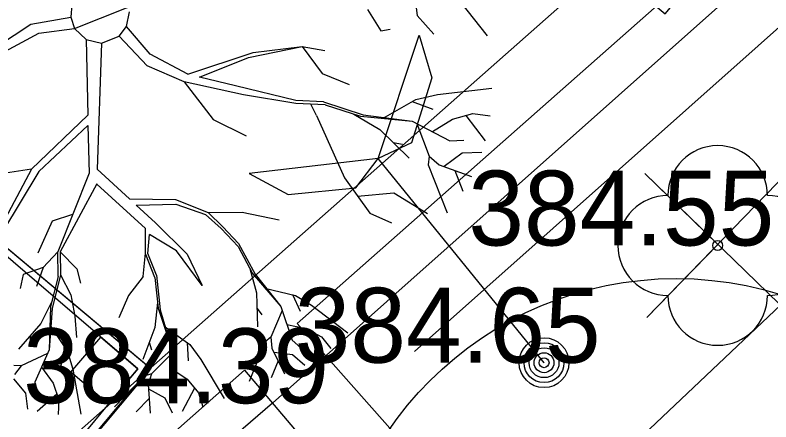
# Model space of a CAD drawing. Extents: x -438233 to -437334, y -1133133 to -1132623.
# Drawn here: x -438067.63 to -438060.06, y -1132995.04 to -1132990.96 of the extents above; entities that cross this region are included whole.
import ezdxf

# ---------------------------------------------------------------- set-up
doc = ezdxf.new("R2010")
doc.units = 0
for name, color, linetype in [('Vrstva 1', 7, 'Continuous'), ('Vrstva 10', 7, 'Continuous'), ('Vrstva 11', 7, 'Continuous'), ('Vrstva 22', 7, 'Continuous'), ('Vrstva 25', 7, 'Continuous'), ('Vrstva 3', 7, 'Continuous'), ('Vrstva 40', 7, 'Continuous'), ('Vrstva 50', 7, 'Continuous'), ('Vrstva 55', 7, 'Continuous'), ('Vrstva 9', 7, 'Continuous')]:
    doc.layers.add(name, color=color, linetype=linetype)

msp = doc.modelspace()

# ---------------------------------------------------------------- linework, layer by layer
at = {"layer": 'Vrstva 1'}
for p, q in [((-438091.5768, -1132973.3017), (-438066.2807, -1132994.4939)), ((-438063.6394, -1132990.6687), (-438063.6015, -1132990.9654)), ((-438063.1685, -1132990.8324), (-438062.8999, -1132991.1694)), ((-438067.0642, -1132990.8541), (-438067.0763, -1132990.9815)), ((-438064.1015, -1132990.9049), (-438063.9684, -1132991.1186)), ((-438067.477, -1132991.0517), (-438067.0763, -1132990.9815)), ((-438067.0763, -1132990.9815), (-438067.0376, -1132991.0961)), ((-438066.5158, -1132991.0767), (-438066.4852, -1132990.9275)), ((-438063.6015, -1132990.9654), (-438063.4346, -1132991.1517)), ((-438067.8141, -1132991.2727), (-438067.477, -1132991.0517)), ((-438067.3972, -1132991.1436), (-438067.0376, -1132991.0961)), ((-438067.0376, -1132991.0961), (-438066.9214, -1132991.2065)), ((-438066.59, -1132991.1719), (-438066.5158, -1132991.0767)), ((-438066.2779, -1132991.3509), (-438066.5158, -1132991.0767)), ((-438063.9684, -1132991.1186), (-438063.8749, -1132991.1009)), ((-438067.7746, -1132991.3468), (-438067.3972, -1132991.1436)), ((-438066.9214, -1132991.2065), (-438066.9045, -1132991.9629)), ((-438066.9214, -1132991.2065), (-438066.7674, -1132991.242)), ((-438066.7674, -1132991.242), (-438066.59, -1132991.1719)), ((-438066.311, -1132991.4678), (-438066.59, -1132991.1719)), ((-438066.7674, -1132991.242), (-438066.8093, -1132992.5048)), ((-438065.2941, -1132991.3864), (-438064.7554, -1132991.2759)), ((-438065.2457, -1132991.3372), (-438064.7554, -1132991.2759)), ((-438064.7554, -1132991.2759), (-438064.5538, -1132991.5476)), ((-438064.7554, -1132991.2759), (-438064.5289, -1132991.317)), ((-438065.9005, -1132991.5541), (-438066.2779, -1132991.3509)), ((-438065.9005, -1132991.5541), (-438065.2457, -1132991.3372)), ((-438065.7844, -1132991.5831), (-438065.2941, -1132991.3864)), ((-438065.9401, -1132991.6283), (-438066.311, -1132991.4678)), ((-438065.4256, -1132991.6702), (-438065.7844, -1132991.5831)), ((-438064.5538, -1132991.5476), (-438064.2845, -1132991.6557)), ((-438065.9401, -1132991.6283), (-438065.6473, -1132992.0065)), ((-438065.3449, -1132991.7597), (-438065.9401, -1132991.6283)), ((-438064.8192, -1132991.8178), (-438065.4256, -1132991.6702)), ((-438063.3999, -1132991.7573), (-438062.8532, -1132991.6928)), ((-438064.8208, -1132991.846), (-438065.3449, -1132991.7597)), ((-438064.5426, -1132991.8299), (-438064.8192, -1132991.8178)), ((-438063.9442, -1132991.9952), (-438063.6176, -1132991.8057)), ((-438063.6176, -1132991.8057), (-438063.3999, -1132991.7573)), ((-438064.524, -1132991.8589), (-438064.8208, -1132991.846)), ((-438064.6111, -1132991.9662), (-438064.6684, -1132991.8525)), ((-438064.5426, -1132991.8299), (-438064.1442, -1132991.9597)), ((-438064.524, -1132991.8589), (-438064.1708, -1132991.9742)), ((-438063.6515, -1132991.825), (-438063.4459, -1132991.9025)), ((-438066.9045, -1132991.9629), (-438067.4706, -1132992.504)), ((-438064.6111, -1132991.9662), (-438064.3329, -1132992.5911)), ((-438064.2377, -1132991.9525), (-438063.9765, -1132992.1065)), ((-438064.1708, -1132991.9742), (-438063.6523, -1132992.0242)), ((-438064.1442, -1132991.9597), (-438063.6523, -1132992.0242)), ((-438063.2499, -1132992.0025), (-438063.0451, -1132991.9468)), ((-438063.1152, -1132991.9662), (-438062.9201, -1132992.2194)), ((-438063.0451, -1132991.9468), (-438062.8693, -1132991.9686)), ((-438065.6473, -1132992.0065), (-438065.3175, -1132992.1702)), ((-438063.6523, -1132992.0242), (-438063.2741, -1132992.2202)), ((-438063.6071, -1132992.0476), (-438063.4829, -1132992.3726)), ((-438063.4499, -1132992.1282), (-438063.2499, -1132992.0025)), ((-438066.9029, -1132992.0678), (-438067.3948, -1132992.529)), ((-438066.9029, -1132992.0678), (-438066.8908, -1132992.5444)), ((-438063.9765, -1132992.1065), (-438063.6845, -1132992.3936)), ((-438063.8426, -1132992.2379), (-438063.7491, -1132992.2532)), ((-438063.2741, -1132992.2202), (-438063.1346, -1132992.2153)), ((-438063.3313, -1132992.4758), (-438063.1523, -1132992.3411)), ((-438063.1523, -1132992.3411), (-438062.9556, -1132992.3331)), ((-438063.4829, -1132992.3726), (-438063.4934, -1132992.4605)), ((-438063.4829, -1132992.3726), (-438063.383, -1132992.4597)), ((-438067.4706, -1132992.504), (-438067.7948, -1132993.1072)), ((-438067.4706, -1132992.504), (-438067.7303, -1132992.5435)), ((-438066.8093, -1132992.5048), (-438066.4868, -1132992.8024)), ((-438063.4934, -1132992.4605), (-438063.3031, -1132992.9411)), ((-438063.383, -1132992.4597), (-438063.0596, -1132992.5782)), ((-438067.3948, -1132992.529), (-438067.7585, -1132993.1306)), ((-438066.8908, -1132992.5444), (-438067.2053, -1132993.333)), ((-438063.2257, -1132992.5177), (-438063.1435, -1132992.7234)), ((-438066.8134, -1132992.6508), (-438067.1819, -1132993.3322)), ((-438066.8142, -1132992.654), (-438066.3255, -1132993.0992)), ((-438064.3329, -1132992.5911), (-438064.0765, -1132992.9459)), ((-438066.4868, -1132992.8024), (-438066.0263, -1132992.8089)), ((-438066.0263, -1132992.8089), (-438065.6997, -1132992.9379)), ((-438064.2015, -1132992.7734), (-438063.8353, -1132992.7403)), ((-438063.8353, -1132992.7403), (-438063.5007, -1132992.9476)), ((-438066.4199, -1132992.8645), (-438066.0207, -1132992.8548)), ((-438066.4199, -1132992.8645), (-438066.2263, -1132993.0427)), ((-438066.0207, -1132992.8548), (-438065.7247, -1132992.958)), ((-438067.0569, -1132992.9596), (-438067.2609, -1132993.0258)), ((-438065.7247, -1132992.958), (-438065.5691, -1132993.0992)), ((-438065.6997, -1132992.9379), (-438065.3578, -1132992.9338)), ((-438065.6997, -1132992.9379), (-438065.5522, -1132993.083)), ((-438065.3578, -1132992.9338), (-438064.9869, -1132993.0129)), ((-438064.0765, -1132992.9459), (-438063.8595, -1132993.0411)), ((-438067.2609, -1132993.0258), (-438067.4061, -1132993.3475)), ((-438066.3247, -1132993.3475), (-438066.3255, -1132993.0992)), ((-438066.2263, -1132993.0427), (-438065.907, -1132993.3564)), ((-438065.3981, -1132993.2782), (-438065.5691, -1132993.0992)), ((-438065.5522, -1132993.083), (-438065.3925, -1132993.25)), ((-438066.3021, -1132993.3508), (-438066.286, -1132993.1588)), ((-438066.0142, -1132993.3209), (-438066.286, -1132993.1588)), ((-438065.3925, -1132993.25), (-438065.228, -1132993.5572)), ((-438067.2053, -1132993.333), (-438067.3529, -1132993.4903)), ((-438067.2005, -1132993.5798), (-438067.2053, -1132993.333)), ((-438067.1819, -1132993.3322), (-438067.0158, -1132993.5015)), ((-438067.1819, -1132993.3322), (-438067.1771, -1132993.5628)), ((-438065.7586, -1132993.6693), (-438066.0142, -1132993.3209)), ((-438065.3981, -1132993.2782), (-438065.2522, -1132993.5507)), ((-438060.59, -1132993.269), (-438060.59, -1132993.269)), ((-438066.3481, -1132993.5782), (-438066.3247, -1132993.3475)), ((-438066.232, -1132993.5886), (-438066.3239, -1132993.3596)), ((-438066.2166, -1132993.5653), (-438066.3021, -1132993.3508)), ((-438065.907, -1132993.3564), (-438065.7586, -1132993.6693)), ((-438067.3529, -1132993.4903), (-438067.552, -1132993.558)), ((-438067.3529, -1132993.4903), (-438067.4198, -1132993.6814)), ((-438067.552, -1132993.558), (-438067.5843, -1132993.6983)), ((-438067.1771, -1132993.5628), (-438067.2634, -1132993.9007)), ((-438067.1771, -1132993.5628), (-438067.0763, -1132993.7628)), ((-438067.0158, -1132993.5015), (-438066.9771, -1132993.6459)), ((-438066.2166, -1132993.5653), (-438066.1796, -1132993.9128)), ((-438065.2796, -1132993.4991), (-438065.2119, -1132993.7435)), ((-438065.2522, -1132993.5507), (-438064.9691, -1132993.8806)), ((-438065.228, -1132993.5572), (-438064.9691, -1132993.8806)), ((-438067.2005, -1132993.5798), (-438067.2771, -1132993.8789)), ((-438066.3481, -1132993.5782), (-438066.4981, -1132993.7701)), ((-438066.232, -1132993.5886), (-438066.1997, -1132993.8967)), ((-438065.1288, -1132993.6951), (-438064.8224, -1132993.7693)), ((-438067.0763, -1132993.7628), (-438067.0359, -1132993.9773)), ((-438066.4981, -1132993.7701), (-438066.5924, -1132993.9943)), ((-438065.2119, -1132993.7435), (-438065.2022, -1132994.0846)), ((-438064.8538, -1132993.7612), (-438064.7748, -1132993.9273)), ((-438064.8224, -1132993.7693), (-438064.6635, -1132993.866)), ((-438067.2625, -1132993.8233), (-438067.3771, -1132994.0491)), ((-438066.2062, -1132993.8386), (-438066.2344, -1132994.0902)), ((-438064.6635, -1132993.866), (-438064.299, -1132994.1434)), ((-438067.2771, -1132993.8789), (-438067.2908, -1132994.3136)), ((-438067.2634, -1132993.9007), (-438067.2908, -1132994.3136)), ((-438066.1997, -1132993.8967), (-438066.061, -1132994.3088)), ((-438066.1796, -1132993.9128), (-438066.061, -1132994.3088)), ((-438065.207, -1132993.8991), (-438065.1595, -1132993.9628)), ((-438064.9554, -1132993.9209), (-438065.0691, -1132994.1878)), ((-438064.9691, -1132993.8806), (-438064.8554, -1132994.2176)), ((-438067.0359, -1132993.9773), (-438067.019, -1132994.191)), ((-438067.3771, -1132994.0491), (-438067.6004, -1132994.3063)), ((-438067.2827, -1132994.0693), (-438067.1077, -1132994.3305)), ((-438066.2344, -1132994.0902), (-438066.3529, -1132994.4096)), ((-438066.1392, -1132994.0765), (-438065.8828, -1132994.2604)), ((-438064.9087, -1132994.0612), (-438064.7151, -1132994.0999)), ((-438067.4787, -1132994.1668), (-438067.4859, -1132994.2459)), ((-438064.7151, -1132994.0999), (-438064.5611, -1132994.1846)), ((-438064.6127, -1132994.1563), (-438064.6417, -1132994.4217)), ((-438066.2884, -1132994.2362), (-438066.2674, -1132994.3128)), ((-438065.9094, -1132994.2418), (-438065.8981, -1132994.4241)), ((-438065.1256, -1132994.2346), (-438065.2885, -1132994.6329)), ((-438065.0691, -1132994.1878), (-438065.1256, -1132994.2346)), ((-438065.0691, -1132994.1878), (-438065.0595, -1132994.2975)), ((-438064.8554, -1132994.2176), (-438064.7692, -1132994.295)), ((-438064.5611, -1132994.1846), (-438064.4668, -1132994.2999)), ((-438067.2908, -1132994.3136), (-438067.4343, -1132994.6394)), ((-438067.1255, -1132994.3039), (-438067.1787, -1132994.4789)), ((-438066.061, -1132994.3088), (-438066.0812, -1132994.6628)), ((-438065.8828, -1132994.2604), (-438065.7715, -1132994.4096)), ((-438065.0595, -1132994.2975), (-438064.9337, -1132994.5555)), ((-438067.3077, -1132994.3523), (-438067.5714, -1132994.4733)), ((-438067.1077, -1132994.3305), (-438067.0553, -1132994.5087)), ((-438066.0626, -1132994.3507), (-438066.2674, -1132994.5555)), ((-438065.0369, -1132994.3378), (-438064.8514, -1132994.3604)), ((-438064.8514, -1132994.3604), (-438064.7288, -1132994.4684)), ((-438067.5714, -1132994.4733), (-438067.6448, -1132994.47)), ((-438067.5714, -1132994.4733), (-438067.6383, -1132994.5612)), ((-438065.7715, -1132994.4096), (-438065.5369, -1132994.8031)), ((-438064.9974, -1132994.4233), (-438065.0675, -1132994.5958)), ((-438062.331, -1132994.443), (-438062.331, -1132994.443)), ((-438066.2871, -1132994.5015), (-438076.5557, -1133006.7587)), ((-438067.3674, -1132994.4886), (-438067.2513, -1132994.6466)), ((-438067.0553, -1132994.5087), (-438066.973, -1132994.9603)), ((-438066.0715, -1132994.4983), (-438065.907, -1132994.6071)), ((-438067.6488, -1132994.6047), (-438067.5279, -1132994.7474)), ((-438066.3384, -1132994.5789), (-438066.6384, -1132994.8861)), ((-438066.2674, -1132994.5555), (-438066.3384, -1132994.5789)), ((-438066.2674, -1132994.5555), (-438066.3005, -1132994.6612)), ((-438065.907, -1132994.6071), (-438065.7957, -1132994.7434)), ((-438067.4343, -1132994.6394), (-438067.4222, -1132994.7555)), ((-438067.2513, -1132994.6466), (-438067.1948, -1132994.8136)), ((-438066.3005, -1132994.6612), (-438066.2804, -1132994.9474)), ((-438066.0812, -1132994.6628), (-438066.0296, -1132994.7676)), ((-438065.8336, -1132994.6974), (-438065.9594, -1132994.9321)), ((-438067.5279, -1132994.7474), (-438067.5109, -1132994.9095)), ((-438067.2142, -1132994.7571), (-438067.4133, -1132994.9329)), ((-438066.2949, -1132994.7063), (-438066.1312, -1132994.7966)), ((-438065.7957, -1132994.7434), (-438065.7522, -1132994.8853)), ((-438067.1948, -1132994.8136), (-438067.2029, -1132994.9619)), ((-438066.29, -1132994.8015), (-438066.4191, -1132994.9345)), ((-438066.1312, -1132994.7966), (-438066.0578, -1132994.9442)), ((-438065.053, -1132994.849), (-438065.053, -1132994.849))]:
    msp.add_line(p, q, dxfattribs=at)
at = {"layer": 'Vrstva 10'}
msp.add_lwpolyline([(-438035.457, -1132968.667), (-438040.579, -1132973.124), (-438048.857, -1132980.452), (-438065.053, -1132994.849), (-438072.69, -1133001.433), (-438073.961, -1133002.24), (-438075.077, -1133002.697), (-438076.272, -1133002.948)], dxfattribs=at)
at = {"layer": 'Vrstva 11'}
msp.add_line((-438064.806, -1132994.051), (-438063.708, -1132995.286), dxfattribs=at)
for points in [[(-438073.986, -1133001.3), (-438049.447, -1132979.638), (-438041.292, -1132972.525), (-438035.024, -1132966.82)], [(-438064.806, -1132994.051), (-438049.025, -1132980.119), (-438040.866, -1132973.003), (-438034.559, -1132967.262)], [(-438062.331, -1132994.443), (-438063.9927, -1132992.3988), (-438063.5813, -1132991.1635), (-438063.455, -1132991.5893), (-438063.6602, -1132992.2393), (-438063.9927, -1132992.3988)], [(-438062.331, -1132994.443), (-438063.9927, -1132992.3988), (-438065.2859, -1132992.5492), (-438064.895, -1132992.7598), (-438064.2167, -1132992.6917), (-438063.9927, -1132992.3988)], [(-438073.562, -1133001.78), (-438065.335, -1132994.517)], [(-438065.335, -1132994.517), (-438064.274, -1132995.768)]]:
    msp.add_lwpolyline(points, dxfattribs=at)
at = {"layer": 'Vrstva 22'}
msp.add_circle((-438060.59, -1132993.269), 0.05, dxfattribs=at)
for centre, start, end in [((-438060.59, -1132992.769), 0, 180), ((-438061.09, -1132993.269), 90, 270), ((-438060.09, -1132993.269), 270, 90), ((-438060.59, -1132993.769), 180, 0)]:
    msp.add_arc(centre, 0.5, start, end, dxfattribs=at)
at = {"layer": 'Vrstva 25'}
for radius in [0.25, 0.2, 0.15, 0.1, 0.05]:
    msp.add_circle((-438062.331, -1132994.443), radius, dxfattribs=at)
at = {"layer": 'Vrstva 40'}
msp.add_line((-438067.0376, -1132991.0961), (-438019.5053, -1132972.094), dxfattribs=at)
for points in [[(-438006.5668, -1132951.3629), (-438080.295, -1133016.157), (-438085.2072, -1133012.0709), (-438080.5464, -1133006.8034), (-438077.1818, -1133006.2314), (-438076.5557, -1133006.7587), (-438075.9136, -1133005.9921), (-438066.4017, -1132994.506), (-438073.0336, -1132988.8171), (-438072.3528, -1132988.0234), (-438069.6652, -1132990.252), (-438068.2866, -1132988.6064), (-438065.6037, -1132990.8541), (-438063.7995, -1132988.7005), (-438061.1166, -1132990.9482), (-438050.7956, -1132978.6286), (-438047.7203, -1132977.5896), (-438045.2045, -1132976.3935), (-438042.6778, -1132974.8844), (-438040.928, -1132973.6336), (-438039.5901, -1132972.5144), (-438037.876, -1132970.8704), (-438035.3972, -1132967.8064), (-438020.0066, -1132954.1238)], [(-438059.7797, -1132992.4242), (-438061.2994, -1132993.9907), (-438060.5883, -1132993.2577), (-438061.3213, -1132992.5466), (-438059.7491, -1132994.0719)]]:
    msp.add_lwpolyline(points, dxfattribs=at)
msp.add_circle((-438061.0061, -1132997.089), 3.4889, dxfattribs=at)
at = {"layer": 'Vrstva 50'}
for points in [[(-438091.5768, -1132973.3017), (-438066.2733, -1132994.5002), (-438069.1631, -1132997.9497), (-438094.4666, -1132976.7512)], [(-438066.7751, -1132994.1871), (-438066.4017, -1132994.506), (-438066.7004, -1132994.8558), (-438067.0738, -1132994.5368)]]:
    msp.add_lwpolyline(points, close=True, dxfattribs=at)
at = {"layer": 'Vrstva 55'}
msp.add_lwpolyline([(-437982.978, -1132924.484), (-438038.365, -1132973.439), (-438076.856, -1133009.846)], dxfattribs=at)
at = {"layer": 'Vrstva 9'}
msp.add_lwpolyline([(-438046.991, -1132979.546), (-438048.487, -1132980.87), (-438063.628, -1132994.33)], dxfattribs=at)

# ---------------------------------------------------------------- texts
at = {"layer": 'Vrstva 3'}
for s, p in [('384.55 ', (-438063.09, -1132993.269)), ('384.65 ', (-438064.831, -1132994.443)), ('384.39 ', (-438067.553, -1132994.849))]:
    msp.add_text(s, height=0.75, dxfattribs=at).set_placement(p)

doc.saveas('drawing.dxf')
